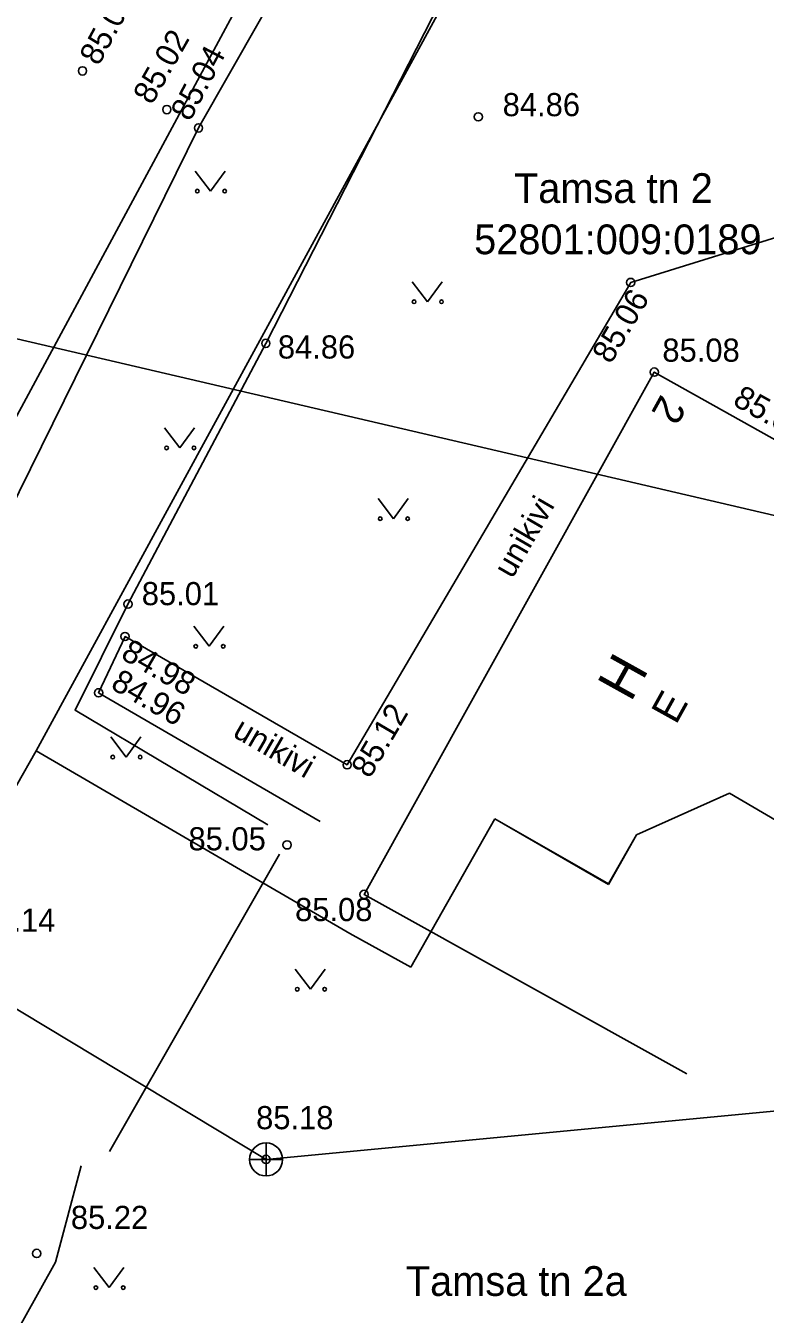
# Model space of a CAD drawing. Extents: x 648748 to 649126, y 6457789 to 6458252.
# Drawn here: x 648911.21 to 648933.59, y 6458153.1 to 6458192.08 of the extents above; entities that cross this region are included whole.
import ezdxf

# ---------------------------------------------------------------- set-up
doc = ezdxf.new("R2010")
doc.units = 0
for name, color, linetype in [('AED', 7, 'Continuous'), ('HALJASTUS', 7, 'Continuous'), ('HOONE', 7, 'Continuous'), ('KKAEV', 7, 'Continuous'), ('KORGUS-EH2000', 7, 'Continuous'), ('KTRASS', 7, 'Continuous'), ('PIIR', 7, 'Continuous'), ('PUU', 7, 'Continuous'), ('SIOHULIIN', 7, 'Continuous'), ('TEE', 7, 'Continuous')]:
    doc.layers.add(name, color=color, linetype=linetype)

msp = doc.modelspace()

# ---------------------------------------------------------------- linework, layer by layer
at = {"layer": 'AED'}
msp.add_lwpolyline([(648940.464, 6458193.018), (648933.165, 6458198.026), (648928.158, 6458201.393), (648924, 6458193.279), (648918.475, 6458182.472), (648914.302, 6458174.583), (648912.702, 6458171.37), (648918.536, 6458167.903)], dxfattribs=at)
at = {"layer": 'HALJASTUS'}
for p, q in [((648916.34, 6458187.687), (648916.803, 6458187.08)), ((648916.803, 6458187.08), (648917.249, 6458187.687)), ((648922.901, 6458184.336), (648923.365, 6458183.73)), ((648923.365, 6458183.73), (648923.81, 6458184.336)), ((648915.409, 6458179.915), (648915.873, 6458179.309)), ((648915.873, 6458179.309), (648916.318, 6458179.915)), ((648921.878, 6458177.775), (648922.341, 6458177.168)), ((648922.341, 6458177.168), (648922.787, 6458177.775)), ((648916.293, 6458173.912), (648916.757, 6458173.306)), ((648916.757, 6458173.306), (648917.202, 6458173.912)), ((648913.781, 6458170.562), (648914.244, 6458169.955)), ((648914.244, 6458169.955), (648914.69, 6458170.562)), ((648919.365, 6458163.535), (648919.828, 6458162.928)), ((648919.828, 6458162.928), (648920.274, 6458163.535)), ((648913.269, 6458154.507), (648913.732, 6458153.901)), ((648913.732, 6458153.901), (648914.178, 6458154.507))]:
    msp.add_line(p, q, dxfattribs=at)
for centre in [(648916.402, 6458187.08), (648917.231, 6458187.08), (648922.964, 6458183.73), (648923.793, 6458183.73), (648915.472, 6458179.309), (648916.301, 6458179.309), (648921.94, 6458177.168), (648922.769, 6458177.168), (648916.356, 6458173.306), (648917.185, 6458173.306), (648913.843, 6458169.955), (648914.672, 6458169.955), (648919.427, 6458162.928), (648920.256, 6458162.928), (648913.331, 6458153.901), (648914.16, 6458153.901)]:
    msp.add_circle(centre, 0.055, dxfattribs=at)
at = {"layer": 'HOONE'}
msp.add_lwpolyline([(648931.219, 6458160.37), (648921.451, 6458165.798), (648930.234, 6458181.603), (648938.475, 6458176.993), (648935.95, 6458172.478), (648942.245, 6458168.957), (648938.513, 6458162.187), (648934.684, 6458164.338)], dxfattribs=at)
at = {"layer": 'KKAEV'}
for p, q in [((648918.483, 6458157.279), (648918.483, 6458158.279)), ((648917.983, 6458157.779), (648918.983, 6458157.779))]:
    msp.add_line(p, q, dxfattribs=at)
msp.add_circle((648918.483, 6458157.779), 0.5, dxfattribs=at)
at = {"layer": 'KORGUS-EH2000'}
for centre in [(648912.926, 6458190.717), (648915.479, 6458189.547), (648924.906, 6458189.326), (648916.438, 6458188.99), (648929.52, 6458184.315), (648918.475, 6458182.472), (648930.234, 6458181.603), (648914.302, 6458174.583), (648914.214, 6458173.602), (648913.413, 6458171.899), (648920.937, 6458169.721), (648919.12, 6458167.298), (648921.451, 6458165.798), (648918.483, 6458157.779), (648911.541, 6458154.935)]:
    msp.add_circle(centre, 0.125, dxfattribs=at)
at = {"layer": 'KTRASS'}
for p, q in [((648918.483, 6458157.779), (648878.199, 6458182.051)), ((648935.747, 6458159.427), (648918.483, 6458157.779))]:
    msp.add_line(p, q, dxfattribs=at)
at = {"layer": 'PIIR'}
for p, q in [((648911.52, 6458170.14), (648929.78, 6458203.63)), ((648905.08, 6458158.8), (648911.52, 6458170.14)), ((648911.52, 6458170.14), (648921.02, 6458164.62)), ((648929.7, 6458167.6), (648932.51, 6458168.86)), ((648932.51, 6458168.86), (648933.92, 6458168.04)), ((648922.87, 6458163.6), (648925.41, 6458168.09)), ((648925.41, 6458168.09), (648928.85, 6458166.1)), ((648928.85, 6458166.12), (648925.41, 6458168.09)), ((648928.85, 6458166.1), (648929.7, 6458167.6)), ((648929.7, 6458167.6), (648928.85, 6458166.12)), ((648921.02, 6458164.62), (648922.87, 6458163.6))]:
    msp.add_line(p, q, dxfattribs=at)
at = {"layer": 'PUU'}
for points in [[(648913.747, 6458158.021), (648918.888, 6458167.017)], [(648909.729, 6458150.414), (648912.112, 6458154.671), (648912.882, 6458157.584)]]:
    msp.add_lwpolyline(points, dxfattribs=at)
at = {"layer": 'SIOHULIIN'}
msp.add_line((648896.343, 6458186.017), (648938.076, 6458176.279), dxfattribs=at)
at = {"layer": 'TEE'}
for points in [[(648891.319, 6458123.494), (648901.175, 6458127.077), (648933.887, 6458139.607), (648944.575, 6458143.741), (648947.822, 6458145.717), (648948.882, 6458147.636), (648949.478, 6458151.73), (648949.531, 6458156.617), (648950.372, 6458161.859), (648951.909, 6458167.68), (648954.505, 6458172.94), (648956.528, 6458180.218), (648952.525, 6458185.448), (648945.526, 6458192.898), (648938.29, 6458202.321), (648932.248, 6458208.399), (648929.676, 6458210.569), (648928.257, 6458209.969), (648926.047, 6458207.531), (648924.786, 6458206.368), (648922.091, 6458200.973), (648909.112, 6458176.906), (648898.467, 6458156.964), (648883.402, 6458130.595)], [(648902.496, 6458156.185), (648903.183, 6458160.572), (648904.191, 6458165.567), (648906.598, 6458170.127), (648910.322, 6458176.61), (648916.438, 6458188.99), (648922.963, 6458200.444), (648925.76, 6458205.755), (648928.587, 6458207.759), (648932.657, 6458207.561), (648933.376, 6458207.264)], [(648920.123, 6458168.002), (648913.413, 6458171.899), (648914.214, 6458173.602), (648920.937, 6458169.721), (648929.52, 6458184.315), (648934.24, 6458185.779), (648935.329, 6458186.492), (648939.887, 6458192.001), (648941.755, 6458196.151), (648943.221, 6458195.17), (648945.249, 6458192.789), (648947.267, 6458190.279), (648944.613, 6458188.214), (648941.907, 6458182.899), (648938.599, 6458177.177), (648938.475, 6458176.993)]]:
    msp.add_lwpolyline(points, dxfattribs=at)

# ---------------------------------------------------------------- texts
at = {"layer": 'HOONE'}
for s, height, rotation, p in [('2', 0.9, 241.0636, (648930.448, 6458180.961)), ('H', 1.2, 60.938, (648929.522, 6458171.591)), ('E', 0.9, 60.938, (648930.892, 6458170.909))]:
    msp.add_text(s, height=height, rotation=rotation, dxfattribs=at).set_placement(p)
at = {"layer": 'KORGUS-EH2000'}
for s, rotation, p in [('85.03', 61.5633, (648913.413, 6458190.843)), ('85.02', 60.2687, (648915.026, 6458189.663)), ('85.04', 62.0919, (648916.177, 6458189.159)), ('85.06', 59.54, (648928.917, 6458181.819)), ('85.07', 330.7793, (648932.575, 6458180.628)), ('84.98', 330.0099, (648914.05, 6458172.954)), ('84.96', 329.8614, (648913.743, 6458172.048)), ('85.12', 59.54, (648921.622, 6458169.279))]:
    msp.add_text(s, height=0.7, rotation=rotation, dxfattribs=at).set_placement(p)
for s, p in [('84.86', (648925.645, 6458189.346)), ('84.86', (648918.839, 6458182.013)), ('85.08', (648930.479, 6458181.917)), ('85.01', (648914.72, 6458174.55)), ('85.05', (648916.134, 6458167.132)), ('85.14', (648909.763, 6458164.669)), ('85.08', (648919.36, 6458164.991)), ('85.18', (648918.181, 6458158.694)), ('85.22', (648912.574, 6458155.676))]:
    msp.add_text(s, height=0.7, dxfattribs=at).set_placement(p)
at = {"layer": 'PIIR'}
for s, p in [('Tamsa tn 2', (648925.987, 6458186.72)), ('52801:009:0189', (648924.781, 6458185.17)), ('Tamsa tn 2a', (648922.713, 6458153.65))]:
    msp.add_text(s, height=0.9, dxfattribs=at).set_placement(p)
at = {"layer": 'TEE'}
for rotation, p in [(59.8614, (648925.935, 6458175.328)), (329.8614, (648917.437, 6458170.598))]:
    msp.add_text('unikivi', height=0.7, rotation=rotation, dxfattribs=at).set_placement(p)

doc.saveas('drawing.dxf')
